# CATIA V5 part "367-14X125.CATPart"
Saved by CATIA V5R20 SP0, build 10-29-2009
Part number: 367-14X125
Definition: NONE
Nomenclature: 367-14X125
Source: Unknown
Description: 367-14X125
Bounding box of the stored display mesh (mm): x 0 to 125, y -14 to 14, z -14 to 14
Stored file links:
  C:\Users\Utente\Desktop\IO LAVORO\3D X SITO CF\X SITO\PLASTICA\3D files 367\367-14X125.CATPart
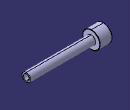
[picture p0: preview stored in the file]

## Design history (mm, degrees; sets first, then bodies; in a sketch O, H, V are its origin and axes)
Body1 "367-14X125" (main body)
  Solid1: solid without history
